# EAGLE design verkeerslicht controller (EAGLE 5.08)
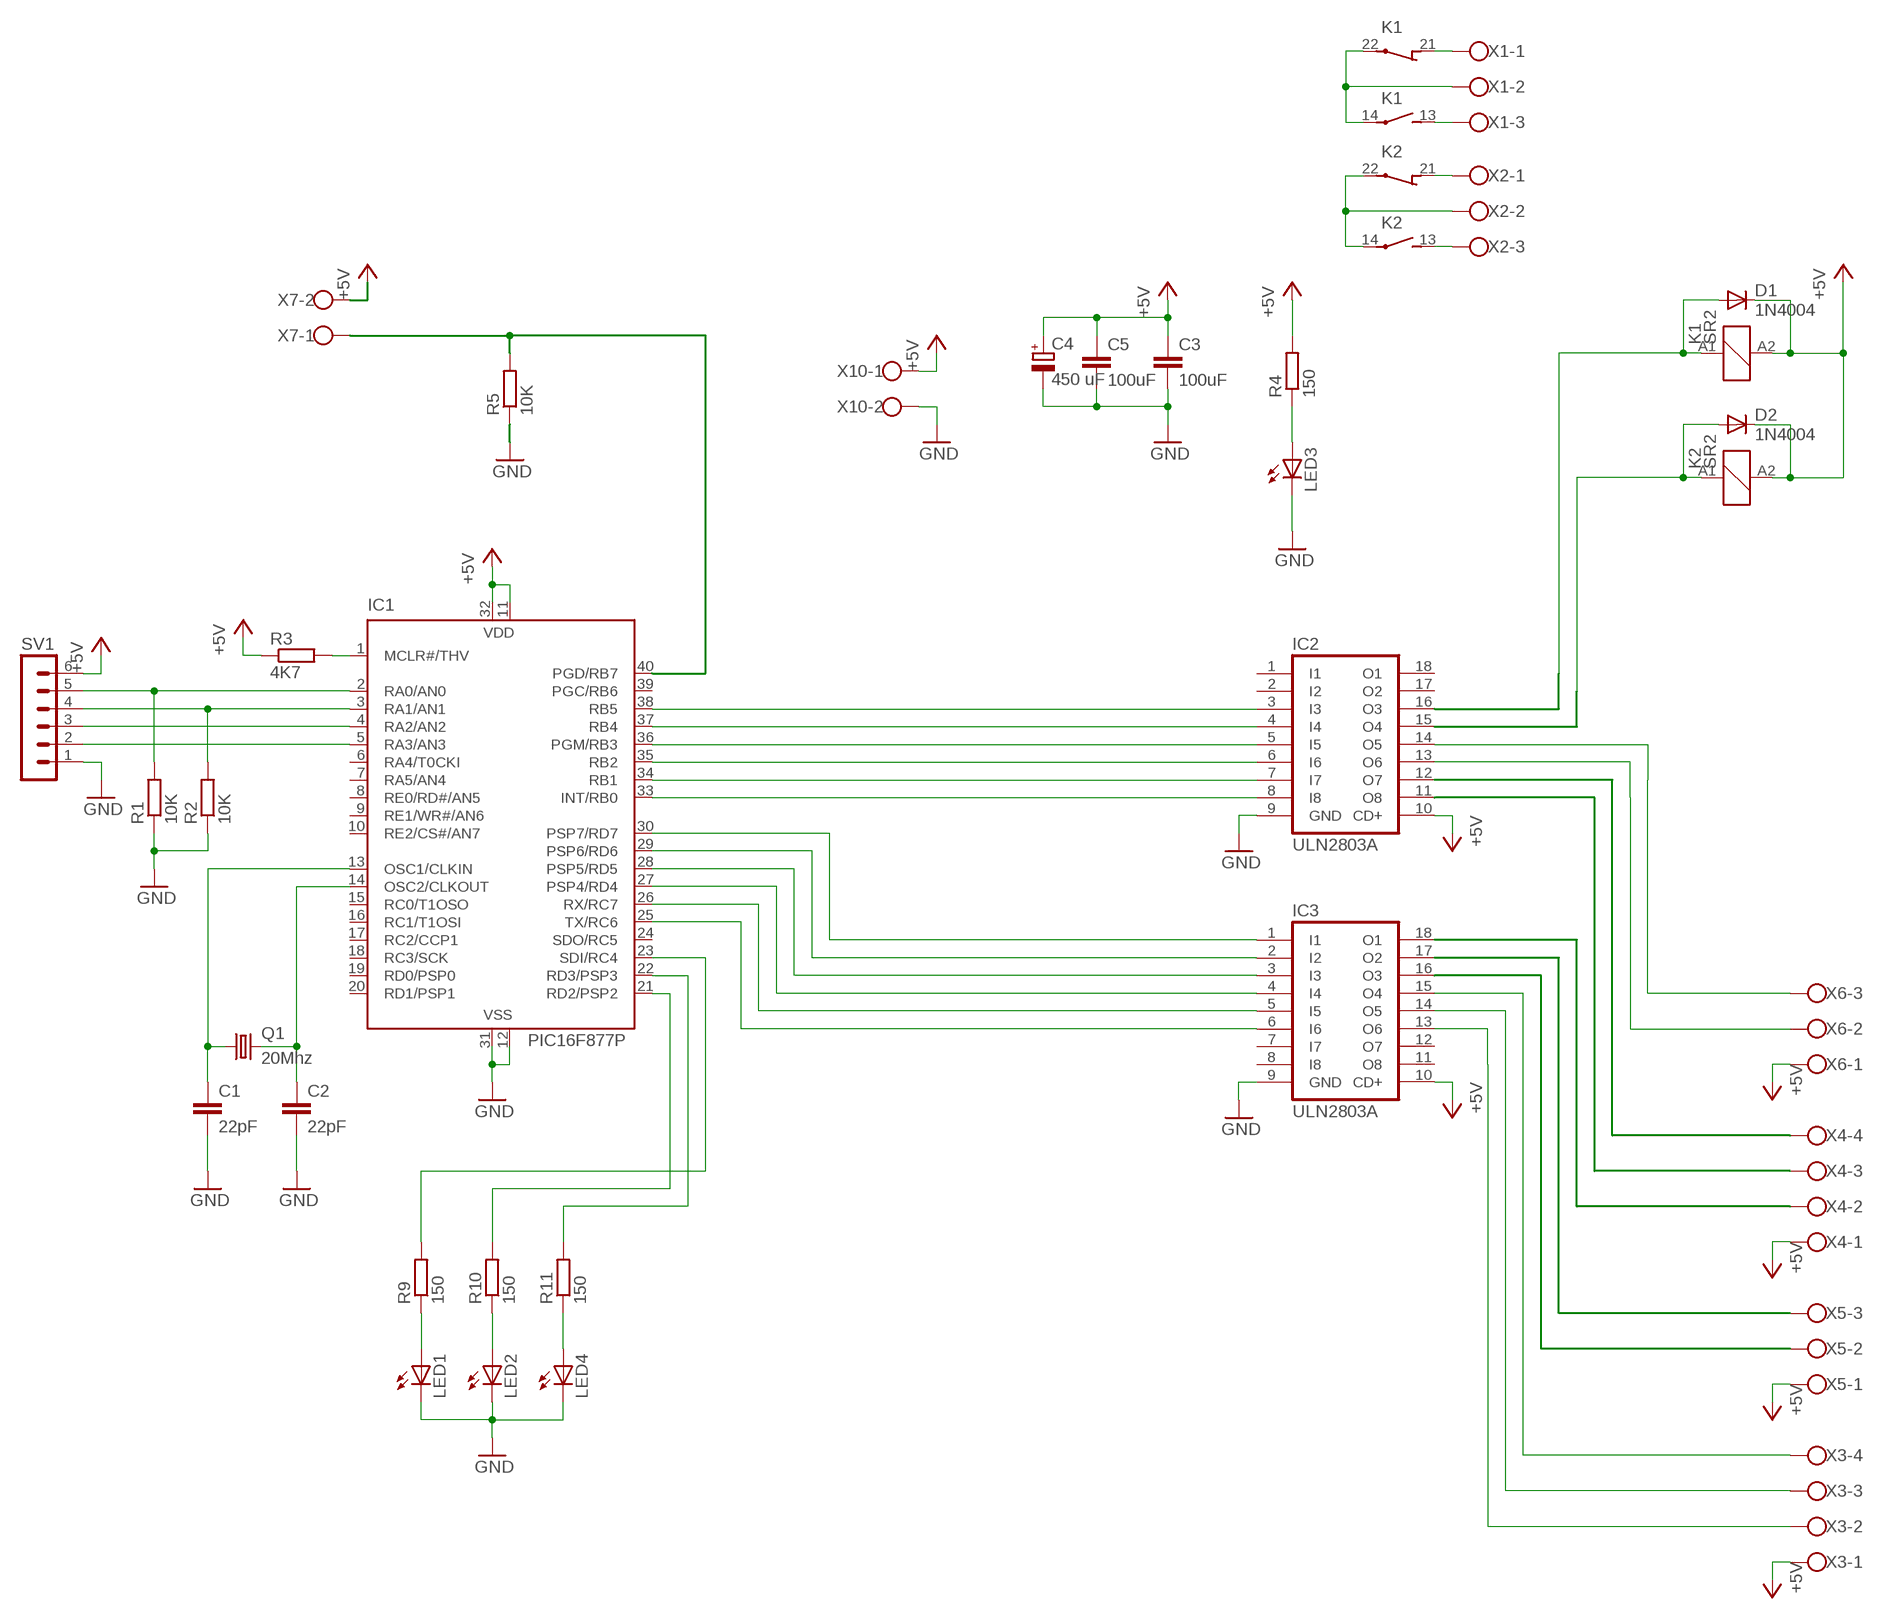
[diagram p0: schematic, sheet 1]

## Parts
C1  22pF  C-EU050-025X075  [C050-025X075]
C2  22pF  C-EU050-025X075  [C050-025X075]
C3  100uF  C-EU050-025X075  [C050-025X075]
C4  450 uF  CPOL-EUE5-13  [E5-13]
C5  100uF  C-EU050-025X075  [C050-025X075]
D1  1N4004  [DO41-10]
D2  1N4004  [DO41-10]
IC1  PIC16F877P  [DIL40]
IC2  ULN2803A  [DIL18]
IC3  ULN2803A  [DIL18]
K1  SR2  SR2X5110  [SR2X]
K2  SR2  SR2X5110  [SR2X]
LED1  LED3MM  [LED3MM]
LED2  LED3MM  [LED3MM]
LED3  LED3MM  [LED3MM]
LED4  LED3MM  [LED3MM]
Q1  20Mhz  CRYSTALHC18U-V  [HC18U-V]
R1  10K  R-EU_0207/7  [0207/7]
R2  10K  R-EU_0207/7  [0207/7]
R3  4K7  R-EU_0207/12  [0207/12]
R4  150  R-EU_0207/7  [0207/7]
R5  10K  R-EU_0207/7  [0207/7]
R9  150  R-EU_0207/2V  [0207/2V]
R10  150  R-EU_0207/2V  [0207/2V]
R11  150  R-EU_0207/2V  [0207/2V]
SV1  MA06-1  [MA06-1]
X1  W237-103  [W237-103]
X2  W237-103  [W237-103]
X3  W237-4  [W237-4]
X4  W237-4  [W237-4]
X5  W237-103  [W237-103]
X6  W237-103  [W237-103]
X7  W237-102  [W237-102]
X10  W237-102  [W237-102]

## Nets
+5V: C3.1 C4.+ C5.1 D1.C D2.C IC1.11(VDD) IC1.32(VDD) IC2.10(CD+) IC3.10(CD+) K1.A2 K2.A2 R3.1 R4.2 SV1.6 X3.1 X4.1 X5.1 X6.1 X7.2 X10.1
GND: C1.2 C2.2 C3.2 C4.- C5.2 IC1.12(VSS) IC1.31(VSS) IC2.9(GND) IC3.9(GND) LED1.K(C) LED2.K(C) LED3.K(C) LED4.K(C) R1.1 R2.1 R5.1 SV1.1 X10.2
N$1: IC1.23(SDI/RC4) R9.2
N$2: IC3.16(O3) X5.2
N$3: IC1.25(TX/RC6) IC3.6(I6)
N$4: IC1.26(RX/RC7) IC3.5(I5)
N$5: IC1.27(PSP4/RD4) IC3.4(I4)
N$6: IC1.28(PSP5/RD5) IC3.3(I3)
N$7: IC1.29(PSP6/RD6) IC3.2(I2)
N$8: IC1.30(PSP7/RD7) IC3.1(I1)
N$9: C1.1 IC1.13(OSC1/CLKIN) Q1.1
N$10: IC3.17(O2) X5.3
N$11: IC3.18(O1) X4.2
N$12: IC1.38(RB5) IC2.3(I3)
N$13: IC1.37(RB4) IC2.4(I4)
N$14: IC1.36(PGM/RB3) IC2.5(I5)
N$15: IC1.35(RB2) IC2.6(I6)
N$16: IC1.34(RB1) IC2.7(I7)
N$17: IC1.33(INT/RB0) IC2.8(I8)
N$18: IC3.13(O6) X3.2
N$19: IC3.14(O5) X3.3
N$20: IC3.15(O4) X3.4
N$21: IC2.11(O8) X4.3
N$22: IC2.12(O7) X4.4
N$23: IC1.40(PGD/RB7) R5.2 X7.1
N$26: IC2.13(O6) X6.2
N$27: IC2.14(O5) X6.3
N$30: C2.1 IC1.14(OSC2/CLKOUT) Q1.2
N$31: IC1.1(MCLR#/THV) R3.2
N$33: IC1.21(RD2/PSP2) R10.2
N$34: LED3.A R4.1
N$35: LED1.A R9.1
N$36: LED2.A R10.1
N$38: D1.A IC2.16(O3) K1.A1
N$39: D2.A IC2.15(O4) K2.A1
N$47: K2.21(2:O) X2.1
N$48: K2.14(3:P) K2.22(2:P) X2.2
N$49: K2.13(3:S) X2.3
N$50: K1.21(2:O) X1.1
N$51: K1.14(3:P) K1.22(2:P) X1.2
N$52: K1.13(3:S) X1.3
N$53: IC1.2(RA0/AN0) R1.2 SV1.5
N$54: IC1.3(RA1/AN1) R2.2 SV1.4
N$55: IC1.4(RA2/AN2) SV1.3
N$56: IC1.5(RA3/AN3) SV1.2
N$72: LED4.A R11.1
N$73: IC1.22(RD3/PSP3) R11.2
Unconnected: IC1.6(RA4/T0CKI) IC1.7(RA5/AN4) IC1.8(RE0/RD#/AN5) IC1.9(RE1/WR#/AN6) IC1.10(RE2/CS#/AN7) IC1.15(RC0/T1OSO) IC1.16(RC1/T1OSI) IC1.17(RC2/CCP1) IC1.18(RC3/SCK) IC1.19(RD0/PSP0) IC1.20(RD1/PSP1) IC1.24(SDO/RC5) IC1.39(PGC/RB6) IC2.1(I1) IC2.2(I2) IC2.17(O2) IC2.18(O1) IC3.7(I7) IC3.8(I8) IC3.11(O8) IC3.12(O7)

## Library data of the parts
C1-C3 C5 = rcl:C-EU: CAPACITOR, European symbol
C4 = rcl:CPOL-EU: POLARIZED CAPACITOR, European symbol
D1 D2 = diode:1N4004: DIODE
IC1 = microchip:PIC16F87*: MICROCONTROLLER
IC2 IC3 = uln-udn:ULN2803A: DRIVER ARRAY
K1 K2 = relay:SR2X5*: Safety Relay 2 pole 6 A SCHRACK Source: http://www.schrack.com/.. 5809.pdf
LED1-LED4 = led:LED: LED
Q1 = crystal:CRYSTAL: CRYSTAL
R1-R5 R9-R11 = rcl:R-EU_: RESISTOR, European symbol
SV1 = con-lstb:MA06-1: PIN HEADER
X1 X2 X5 X6 = con-wago-500:W237-103: WAGO SCREW CLAMP
X3 X4 = con-wago-500:W237-4: WAGO SCREW CLAMP
X7 X10 = con-wago-500:W237-102: WAGO SCREW CLAMP

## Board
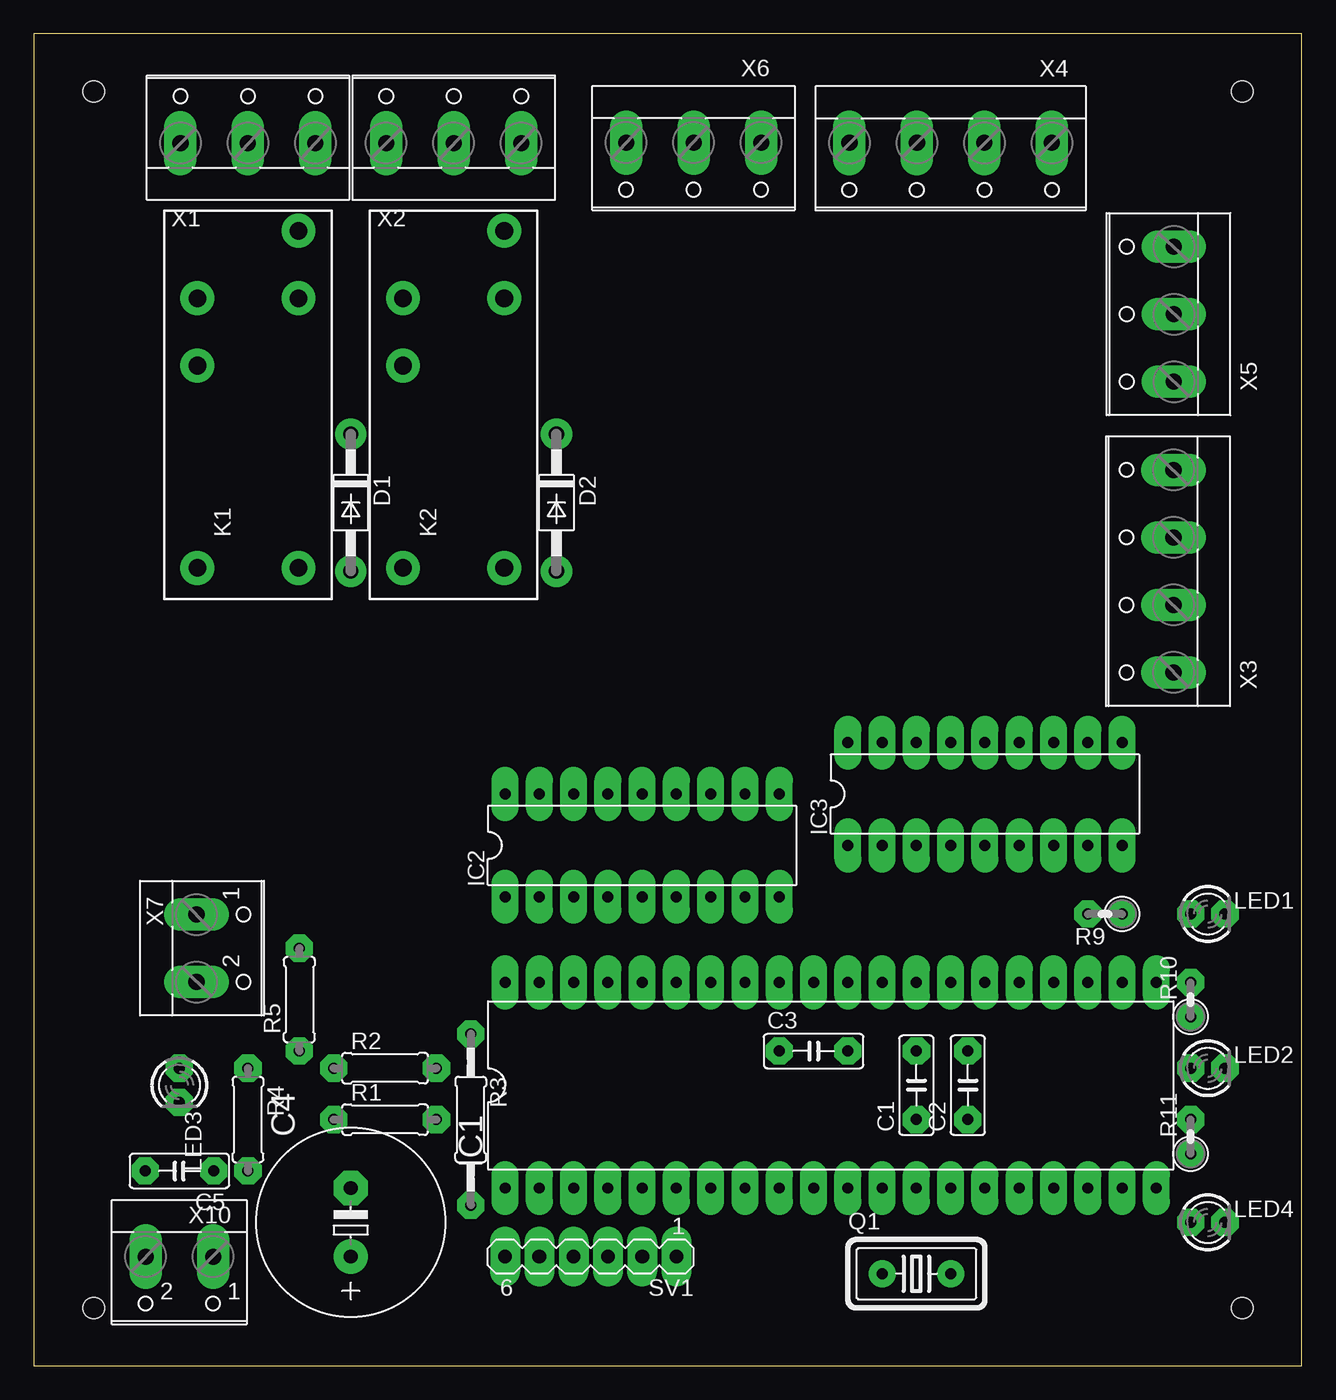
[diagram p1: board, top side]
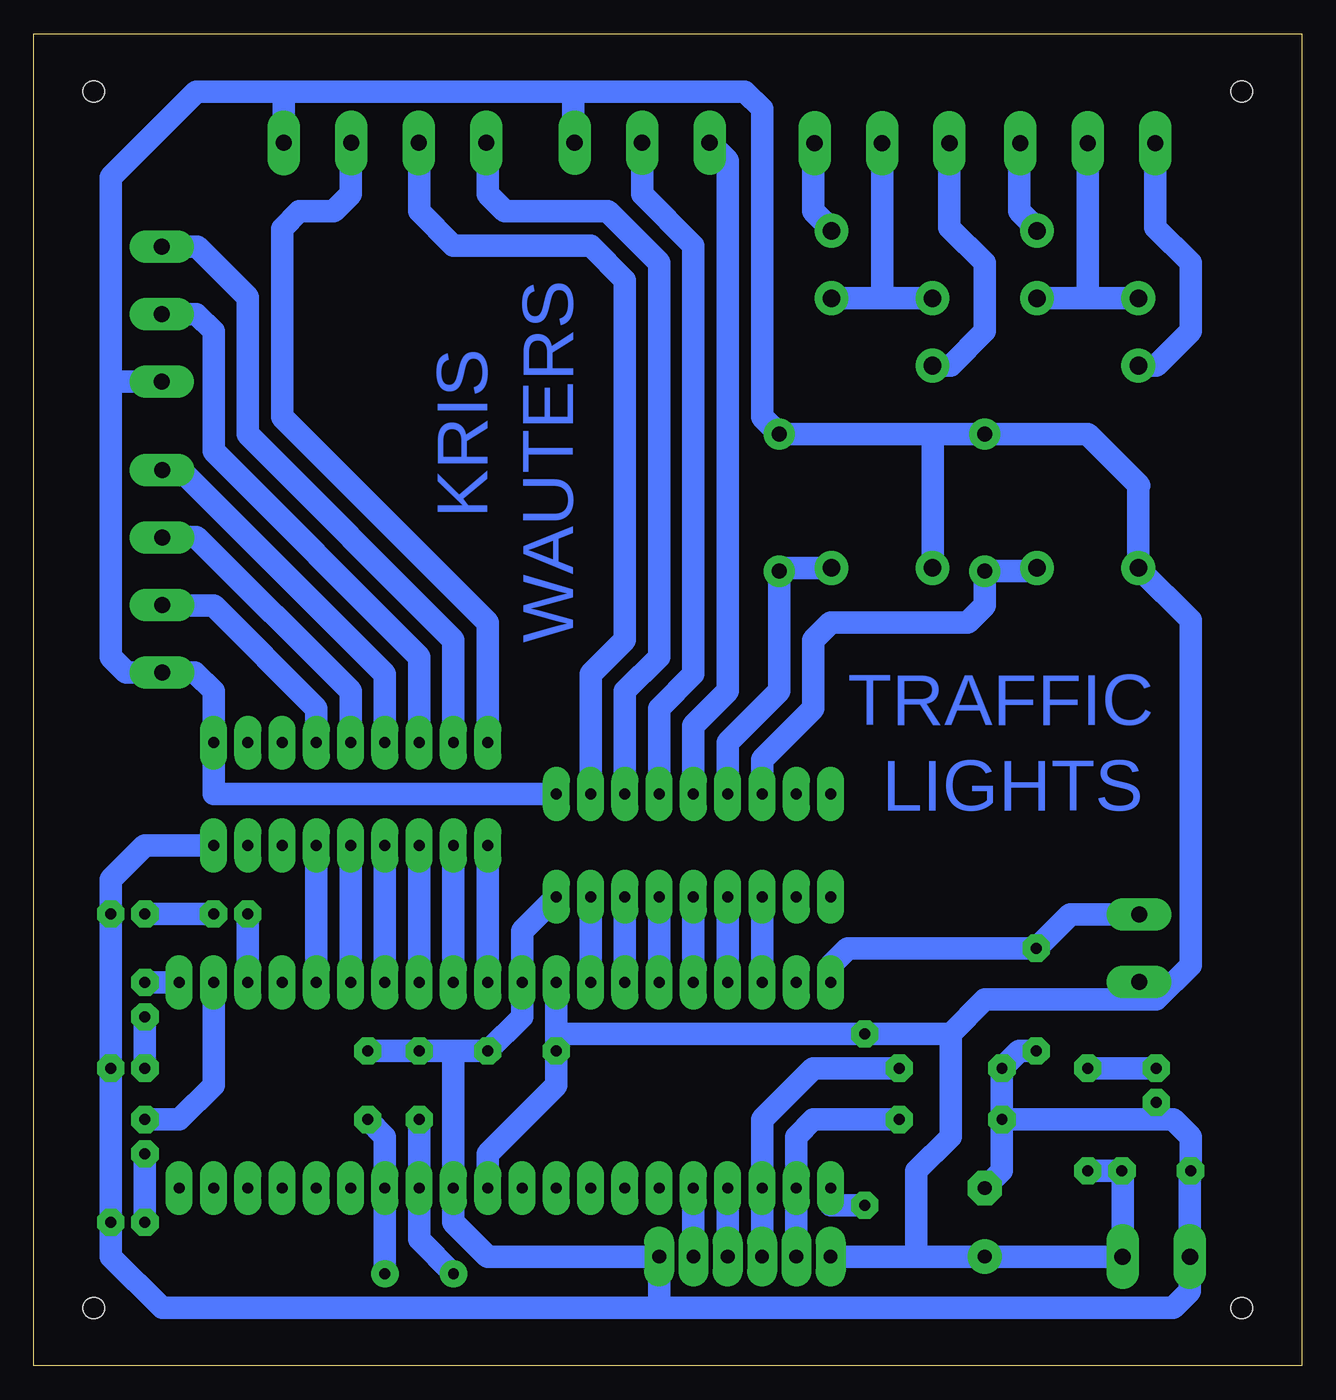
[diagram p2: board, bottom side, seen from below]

Size 93.96 x 98.73 mm. Coordinates in mm from the lower left corner, seen from the top.
Outline: 0,0 93.96,0 93.96,98.73 0,98.73 0,0
Copper layers (1*16): Top 1mm / dielectric 1.5mm / Bottom 1mm
Design rules "DRC settings middle": minimum track width 1.2mm, minimum drill 24mil, track to track 0.4mm, track to pad 0.4mm, pad to pad 0.4mm, via to via 0.4mm, smd to smd 8mil, copper to edge 0.5mm, drill to drill 0.5mm, minimum pad ring 0.6mm, minimum via ring 1mm, stop-mask expansion 4mil, vias tented up to drill 0mil, thermal gap 10mil
Holes 1.6 mm at 4.44,94.45 4.44,4.28 89.53,4.28 89.53,94.45

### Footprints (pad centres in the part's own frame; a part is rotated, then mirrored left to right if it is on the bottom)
C050-025X075 = drill 0.813 octagon: 1 -2.54,0; 2 2.54,0
E5-13 = drill 1.016 pad 2.54 round: + -2.54,0 | drill 1.016 pad 2.54 octagon: - 2.54,0
DO41-10 = drill 1.118 round: A 5.08,0; C -5.08,0
DIL40 = drill 0.813 long: 1 -24.13,-7.62; 2 -21.59,-7.62; 3 -19.05,-7.62; 4 -16.51,-7.62; 5 -13.97,-7.62; 6 -11.43,-7.62; 7 -8.89,-7.62; 8 -6.35,-7.62; 9 -3.81,-7.62; 10 -1.27,-7.62; 11 1.27,-7.62; 12 3.81,-7.62; 13 6.35,-7.62; 14 8.89,-7.62; 15 11.43,-7.62; 16 13.97,-7.62; 17 16.51,-7.62; 18 19.05,-7.62; 19 21.59,-7.62; 20 24.13,-7.62; 21 24.13,7.62; 22 21.59,7.62; 23 19.05,7.62; 24 16.51,7.62; 25 13.97,7.62; 26 11.43,7.62; 27 8.89,7.62; 28 6.35,7.62; 29 3.81,7.62; 30 1.27,7.62; 31 -1.27,7.62; 32 -3.81,7.62; 33 -6.35,7.62; 34 -8.89,7.62; 35 -11.43,7.62; 36 -13.97,7.62; 37 -16.51,7.62; 38 -19.05,7.62; 39 -21.59,7.62; 40 -24.13,7.62
DIL18 = drill 0.813 long: 1 -10.16,-3.81; 2 -7.62,-3.81; 3 -5.08,-3.81; 4 -2.54,-3.81; 5 0,-3.81; 6 2.54,-3.81; 7 5.08,-3.81; 8 7.62,-3.81; 9 10.16,-3.81; 10 10.16,3.81; 11 7.62,3.81; 12 5.08,3.81; 13 2.54,3.81; 14 0,3.81; 15 -2.54,3.81; 16 -5.08,3.81; 17 -7.62,3.81; 18 -10.16,3.81
SR2X = drill 1.3 round: 13 12.54,-3.75; 14 7.54,-3.75; 21 2.54,3.75; 22 7.54,3.75; A1 -12.46,-3.75; A2 -12.46,3.75
LED3MM = drill 0.813 octagon: A -1.27,0; K 1.27,0
HC18U-V = drill 0.813 round: 1 -2.54,0; 2 2.54,0
0207/7 = drill 0.813 octagon: 1 -3.81,0; 2 3.81,0
0207/12 = drill 0.813 octagon: 1 -6.35,0; 2 6.35,0
0207/2V = drill 0.813 octagon: 1 -1.27,0; 2 1.27,0
MA06-1 = drill 1.016 long: 1 -6.35,0; 2 -3.81,0; 3 -1.27,0; 4 1.27,0; 5 3.81,0; 6 6.35,0
W237-103 = drill 1.194 long: 1 -5,-1.29; 2 0,-1.29; 3 5,-1.29
W237-4 = drill 1.194 long: 1 -7.5,-1.27; 2 -2.5,-1.27; 3 2.5,-1.27; 4 7.5,-1.27
W237-102 = drill 1.194 long: 1 -2.5,-1.27; 2 2.5,-1.27

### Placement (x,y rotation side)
C1  65.4,20.79 90 top
C2  69.21,20.79 90 top
C3  57.78,23.33 0 top
C4  23.49,10.63 90 top
C5  10.79,14.44 180 top
D1  23.49,63.97 270 top
D2  38.73,63.97 270 top
IC1  59.05,20.79 0 top
IC2  45.08,38.57 0 top
IC3  70.48,42.38 0 top
K1  15.87,71.59 90 top
K2  31.11,71.59 90 top
LED1  86.99,33.49 0 top
LED2  86.99,22.06 0 top
LED3  10.79,20.79 270 top
LED4  86.99,10.63 0 top
Q1  65.4,6.82 0 top
R1  26.03,18.25 0 top
R2  26.03,22.06 0 top
R3  32.38,18.25 270 top
R4  15.87,18.25 270 top
R5  19.68,27.14 90 top
R9  79.37,33.49 180 top
R10  85.72,27.14 90 top
R11  85.72,16.98 90 top
SV1  41.27,8.09 180 top
X1  15.87,91.91 0 top
X2  31.11,91.91 0 top
X3  83.18,58.89 90 top
X4  67.94,89.37 180 top
X5  83.18,77.94 90 top
X6  48.89,89.37 180 top
X7  13.33,30.95 270 top
X10  10.79,6.82 180 top

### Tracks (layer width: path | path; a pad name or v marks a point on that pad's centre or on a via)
+5V
  Bottom 1.676: IC1.11 60.32,15.71 55.24,20.79 C3.1 55.24,24.6 | 27.3,69.05 D1.C 15.87,69.05 12.06,65.24 12.12,65.18 K1.A2 | 27.3,69.05 D2.C 40,70.32 40,93.18 41.27,94.45 53.97,94.45 | K2.A2 27.36,67.72 27.3,69.05 | 55.24,24.6 IC1.32 | 55.24,24.6 R3.1 26.03,24.6 | 28.57,8.09 C4.+ X10.1 13.29,14.4 C5.1 R4.2 | 28.57,8.09 SV1.6 | 88.26,72.86 88.26,88.1 81.91,94.45 75.56,94.45 | 88.26,72.86 88.26,52.54 87.11,51.39 X3.1 82.03,51.39 80.64,50 IC3.10 80.64,42.38 IC2.10 | 53.97,94.45 75.56,94.45 | 53.97,94.45 53.97,90.64 53.91,90.64 X6.1 | X4.1 75.44,94.33 75.56,94.45 | X5.1 88.18,72.94 88.26,72.86 | 26.03,24.6 23.49,27.14 12.06,27.14 | K1.A2 12.06,59.07 | 12.06,27.14 10.79,27.14 8.25,29.68 8.25,55.26 K1.A2 | 26.03,24.6 26.03,16.98 28.57,14.44 28.57,8.09 | 12.06,27.14 X7.2
GND
  Bottom 1.676: 62.86,23.33 C3.2 57.78,25.87 IC1.31 57.78,32.22 IC2.9 | 62.86,23.33 C1.2 C2.2 | 62.86,23.33 IC1.12 62.86,10.63 60.32,8.09 SV1.1 47.62,4.28 | R1.1 R2.1 20.95,23.33 R5.1 | 10.79,18.25 9.52,18.25 8.25,16.98 C5.2 8.29,14.4 X10.2 8.29,5.51 9.52,4.28 47.62,4.28 | 10.79,18.25 LED3.K | 47.62,4.28 84.45,4.28 88.26,8.09 LED4.K LED2.K LED1.K 88.26,36.03 85.72,38.57 IC3.9 | 10.79,18.25 R1.1 | R1.1 22.22,14.44 C4.-
N$1
  Bottom 1.676: IC1.23 R9.2
N$2
  Bottom 1.676: X5.2 81.91,77.94 80.64,76.67 80.64,67.78 65.4,52.54 IC3.16
N$3
  Bottom 1.676: IC1.25 IC3.6
N$4
  Bottom 1.676: IC1.26 IC3.5
N$5
  Bottom 1.676: IC1.27 IC3.4
N$6
  Bottom 1.676: IC1.28 IC3.3
N$7
  Bottom 1.676: IC1.29 IC3.2
N$8
  Bottom 1.676: IC1.30 IC3.1
N$9
  Bottom 1.676: C1.1 IC1.13 65.4,9.36 Q1.1
N$10
  Bottom 1.676: X5.3 81.83,82.94 78.1,79.21 78.1,69.05 62.86,53.81 IC3.17
N$11
  Bottom 1.676: IC3.18 60.32,55.08 75.56,70.32 75.56,84.29 74.29,85.56 71.75,85.56 70.48,86.83 70.48,90.6 X4.2
N$12
  Bottom 1.676: IC1.38 IC2.3
N$13
  Bottom 1.676: IC1.37 IC2.4
N$14
  Bottom 1.676: IC1.36 IC2.5
N$15
  Bottom 1.676: IC1.35 IC2.6
N$16
  Bottom 1.676: IC1.34 IC2.7
N$17
  Bottom 1.676: IC1.33 IC2.8
N$18
  Bottom 1.676: IC3.13 73.02,48.73 80.64,56.35 84.45,56.35 X3.2
N$19
  Bottom 1.676: IC3.14 70.48,50 81.91,61.43 84.41,61.43 X3.3
N$20
  Bottom 1.676: IC3.15 67.94,51.27 83.18,66.51 84.33,66.51 X3.4
N$21
  Bottom 1.676: IC2.11 52.7,51.27 50.16,53.81 50.16,80.48 52.7,83.02 62.86,83.02 65.4,85.56 65.4,90.6 X4.3
N$22
  Bottom 1.676: IC2.12 50.16,50 47.62,52.54 47.62,81.75 51.43,85.56 59.05,85.56 60.32,86.83 60.32,90.52 X4.4
N$23
  Bottom 1.676: IC1.40 34.92,29.68 33.65,30.95 R5.2 17.18,33.45 X7.1
N$26
  Bottom 1.676: IC2.13 47.62,48.73 45.08,51.27 45.08,83.02 48.89,86.83 X6.2
N$27
  Bottom 1.676: IC2.14 45.08,47.46 42.54,50 42.54,89.31 X6.3
N$30
  Bottom 1.676: Q1.2 IC1.14 67.94,16.98 C2.1
N$31
  Bottom 1.676: R3.2 34.92,11.9 IC1.1
N$33
  Bottom 1.676: IC1.21 R10.2
N$34
  Bottom 1.676: LED3.A R4.1
N$35
  Bottom 1.676: R9.1 LED1.A
N$36
  Bottom 1.676: LED2.A R10.1
N$38
  Bottom 1.676: K1.A1 19.86,58.89 D1.A 23.49,56.35 24.76,55.08 34.92,55.08 36.19,53.81 36.19,48.73 40,44.92 IC2.16
N$39
  Bottom 1.676: K2.A1 38.49,59.13 D2.A 38.73,50 42.54,46.19 IC2.15
N$47
  Bottom 1.676: X2.1 26.11,84.37 23.49,81.75 23.49,76.67 26.03,74.13 K2.21
N$48
  Bottom 1.676: K2.22 31.11,79.13 | 31.11,79.13 K2.14 | 31.11,79.13 X2.2
N$49
  Bottom 1.676: K2.13 34.86,84.23 36.19,85.56 36.19,90.54 X2.3
N$50
  Bottom 1.676: X1.1 10.87,84.37 8.25,81.75 8.25,76.67 10.79,74.13 K1.21
N$51
  Bottom 1.676: K1.22 15.87,79.13 | 15.87,79.13 K1.14 | 15.87,79.13 X1.2
N$52
  Bottom 1.676: K1.13 19.62,84.23 20.95,85.56 20.95,90.54 X1.3
N$53
  Bottom 1.676: SV1.5 IC1.2 37.46,16.98 36.19,18.25 R1.2
N$54
  Bottom 1.676: SV1.4 IC1.3 40,18.25 36.19,22.06 R2.2
N$55
  Bottom 1.676: SV1.3 IC1.4
N$56
  Bottom 1.676: SV1.2 IC1.5
N$72
  Bottom 1.676: LED4.A R11.1
N$73
  Bottom 1.676: R11.2 83.18,18.25 80.64,20.79 IC1.22

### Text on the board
Bottom: WAUTERS | KRIS | TRAFFIC | LIGHTS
